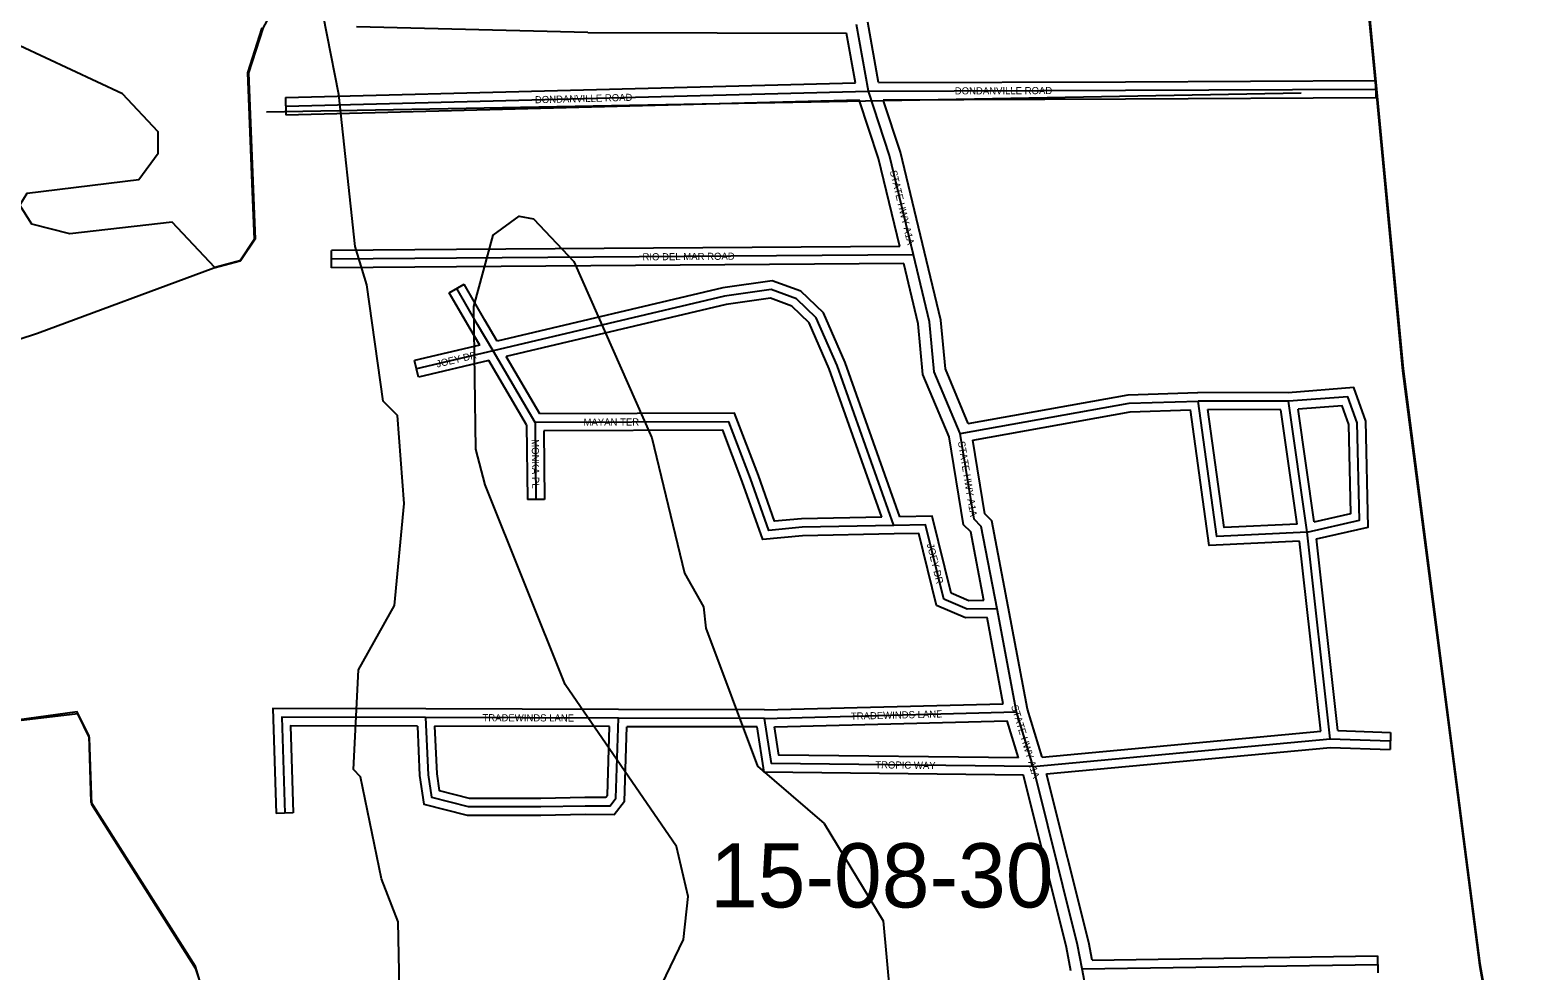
# Model space of a CAD drawing. Extents: x 418523 to 616617, y 1878279 to 2196743.
# Drawn here: x 568098 to 573384, y 1989941 to 1993241 of the extents above; entities that cross this region are included whole.
import ezdxf

# ---------------------------------------------------------------- set-up
doc = ezdxf.new("R2010")
doc.units = 0
for name, color, linetype in [('Level 1', 7, 'Continuous'), ('Level 2', 7, 'Continuous'), ('Level 22', 7, 'Continuous'), ('Level 23', 7, 'Continuous'), ('Level 31', 7, 'Continuous'), ('Level 32', 7, 'Continuous'), ('Level 34', 7, 'Continuous'), ('Level 5', 7, 'Continuous'), ('Level 7', 7, 'Continuous'), ('Level 8', 7, 'Continuous')]:
    doc.layers.add(name, color=color, linetype=linetype)

msp = doc.modelspace()

# ---------------------------------------------------------------- linework, layer by layer
at = {"layer": 'Level 1'}
msp.add_line((572554.585, 1993020.008), (568926.609, 1992952.584), dxfattribs=at)
at = {"layer": 'Level 22'}
for p, q in [((571037.193, 1993026.716), (570995.871, 1993260.28)), ((571556.415, 1990849.401), (571488.107, 1991210.667)), ((571614.332, 1990657.621), (571556.415, 1990849.401))]:
    msp.add_line(p, q, dxfattribs=at)
for points in [[(571195.387, 1992452.501), (571111.516, 1992801.441), (571037.193, 1993026.716)], [(571358.857, 1991825.544), (571267.7, 1992042.493), (571251.613, 1992217.449), (571195.387, 1992452.501)], [(571488.107, 1991210.667), (571432.954, 1991500.265), (571408.274, 1991525.051), (571358.857, 1991825.544)], [(571786.51, 1989948.824), (571770.843, 1990032.137), (571614.332, 1990657.621)], [(572009.84, 1988997.717), (571869.755, 1989598.069), (571844.796, 1989639.947), (571786.51, 1989948.824)]]:
    msp.add_lwpolyline(points, dxfattribs=at)
at = {"layer": 'Level 23'}
for p, q in [((571072.487, 1993056.834), (571035.009, 1993268.671)), ((570991.47, 1993055.547), (570960.539, 1993230.374)), ((571510.256, 1990878.225), (571453.148, 1991180.257)), ((571595.325, 1990858.924), (571527.412, 1991218.099)), ((571563.304, 1990688.226), (571523.946, 1990818.556)), ((571646.122, 1990690.718), (571595.324, 1990858.923))]:
    msp.add_line(p, q, dxfattribs=at)
for points in [[(571147.12, 1992482.155), (571073.01, 1992790.481), (571005.245, 1992995.881)], [(571234.279, 1992461.849), (571150.022, 1992812.4), (571089.156, 1992996.889)], [(571387.287, 1991861.144), (571306.969, 1992052.3), (571291.183, 1992223.966), (571234.289, 1992461.806)], [(571320.153, 1991814.397), (571228.433, 1992032.687), (571212.043, 1992210.931), (571161.493, 1992422.254)], [(571441.777, 1991240.13), (571395.954, 1991480.732), (571370.884, 1991505.91), (571320.153, 1991814.397)], [(571527.402, 1991218.151), (571469.954, 1991519.797), (571445.664, 1991544.191), (571403.099, 1991803.025)], [(571747.199, 1989941.432), (571731.75, 1990023.578), (571580.506, 1990628.017)], [(571821.476, 1989979.336), (571809.935, 1990040.696), (571661.994, 1990631.936)]]:
    msp.add_lwpolyline(points, dxfattribs=at)
at = {"layer": 'Level 31'}
for p, q in [((568994.381, 1992974.052), (571037.193, 1993026.716)), ((571195.387, 1992452.501), (569593.469, 1992440.97)), ((569593.469, 1992440.97), (569155.17, 1992437.641)), ((569721.149, 1992115.924), (569453.329, 1992052.916)), ((569868.668, 1991865.018), (569721.149, 1992115.924)), ((572509.728, 1991938.911), (572192.9, 1991939.997)), ((572575.288, 1991480.191), (572509.728, 1991938.911)), ((569868.668, 1991865.018), (569871.523, 1991594.815)), ((572656.419, 1990754.878), (572575.288, 1991480.191)), ((570160.875, 1990827.913), (569485.018, 1990829.866)), ((570672.764, 1990826.718), (570160.875, 1990827.913)), ((570672.764, 1990826.718), (571556.415, 1990849.401)), ((571614.332, 1990657.621), (572656.419, 1990754.878)), ((572656.419, 1990754.878), (572866.995, 1990747.854)), ((571786.51, 1989948.824), (572822.721, 1989963.914))]:
    msp.add_line(p, q, dxfattribs=at)
for points in [[(571037.193, 1993026.716), (571938.505, 1993029.729), (572815.719, 1993034.272)], [(569721.149, 1992115.924), (569666.818, 1992208.421), (569593.854, 1992334.781)], [(571126.594, 1991503.882), (570927.769, 1992064.01), (570854.58, 1992231.461), (570784.647, 1992298.9), (570696.873, 1992331.106), (570532.855, 1992307.851), (569721.149, 1992115.924)], [(571358.857, 1991825.544), (571951.216, 1991932.186), (572192.9, 1991939.997)], [(572575.288, 1991480.191), (572258.418, 1991464.55), (572192.9, 1991939.997)], [(572575.288, 1991480.191), (572758.694, 1991521.595), (572751.224, 1991863.447), (572718.131, 1991955.164), (572509.728, 1991938.911)], [(571126.594, 1991503.882), (570804.671, 1991497.356), (570687.616, 1991485.991), (570623.339, 1991667.969), (570547.371, 1991867.43), (569868.668, 1991865.018)], [(571488.107, 1991210.667), (571383.76, 1991209.454), (571302.017, 1991244.917), (571237.603, 1991506.171), (571126.594, 1991503.882)], [(569485.018, 1990829.866), (568980.424, 1990831.424), (568990.727, 1990494.655)], [(569485.018, 1990829.866), (569493.743, 1990629.471), (569505.609, 1990550.166), (569634.299, 1990517.498), (569888.661, 1990517.626), (570043.759, 1990520.536), (570131.612, 1990520.33), (570151.972, 1990546.829), (570160.875, 1990827.913)], [(571614.332, 1990657.621), (570697.135, 1990668.471), (570672.764, 1990826.718)]]:
    msp.add_lwpolyline(points, dxfattribs=at)
at = {"layer": 'Level 32'}
for p, q in [((570053.59, 1993232.839), (569242.097, 1993251.894)), ((570053.59, 1993232.84), (570960.54, 1993230.374)), ((568993.608, 1993004.043), (570991.47, 1993055.548)), ((572815.564, 1993064.273), (572815.874, 1993004.271)), ((568993.608, 1993004.043), (568995.154, 1992944.061)), ((568995.154, 1992944.061), (571005.245, 1992995.881)), ((569593.242, 1992470.968), (569154.943, 1992467.641)), ((569155.398, 1992407.641), (569154.943, 1992467.641)), ((571147.12, 1992482.155), (569593.254, 1992470.97)), ((569593.698, 1992410.97), (569155.398, 1992407.641)), ((571161.493, 1992422.254), (569593.686, 1992410.969)), ((569567.874, 1992319.78), (569619.834, 1992349.783)), ((569674.676, 1992135.81), (569446.46, 1992082.119)), ((569460.2, 1992023.711), (569446.46, 1992082.119)), ((569706.495, 1992081.656), (569460.2, 1992023.711)), ((569838.755, 1991856.706), (569706.496, 1992081.656)), ((569885.795, 1991895.079), (569767.616, 1992096.082)), ((572508.611, 1991968.915), (572192.467, 1991969.999)), ((572483.699, 1991908.999), (572227.336, 1991909.878)), ((572540.933, 1991508.532), (572483.699, 1991908.999)), ((572600.389, 1991516.613), (572543.954, 1991911.487)), ((569838.755, 1991856.706), (569841.524, 1991594.497)), ((569898.987, 1991835.124), (569901.522, 1991595.131)), ((569901.522, 1991595.131), (569841.524, 1991594.497)), ((572623.208, 1990781.908), (572548.609, 1991448.836)), ((572683.349, 1990783.996), (572608.088, 1991456.84)), ((570672.414, 1990856.719), (571510.256, 1990878.226)), ((570160.962, 1990857.913), (569485.104, 1990859.866)), ((570672.415, 1990856.719), (570160.945, 1990857.913)), ((570707.604, 1990797.601), (571523.946, 1990818.555)), ((570129.913, 1990798.001), (569516.358, 1990799.775)), ((570647.021, 1990796.777), (570189.939, 1990797.844)), ((571646.123, 1990690.718), (572623.208, 1990781.909)), ((572683.35, 1990783.996), (572867.995, 1990777.837)), ((572867.995, 1990777.837), (572865.996, 1990717.87)), ((571661.993, 1990631.936), (572657.316, 1990724.83)), ((572657.317, 1990724.831), (572865.996, 1990717.87)), ((569020.713, 1990495.572), (568960.74, 1990493.738)), ((571821.476, 1989979.337), (572822.285, 1989993.911)), ((572822.285, 1989993.911), (572823.159, 1989933.916))]:
    msp.add_line(p, q, dxfattribs=at)
for points in [[(571072.487, 1993056.834), (571938.378, 1993059.73), (572815.564, 1993064.273)], [(571089.155, 1992996.889), (571938.634, 1992999.728), (572815.874, 1993004.271)], [(569735.8, 1992150.215), (569692.743, 1992223.518), (569619.834, 1992349.783)], [(571147.624, 1991534.321), (570955.686, 1992075.049), (570879.687, 1992248.926), (570800.919, 1992324.886), (570700.127, 1992361.868), (570527.286, 1992337.361), (569735.8, 1992150.216)], [(569674.676, 1992135.81), (569640.894, 1992193.322), (569567.874, 1992319.78)], [(571084.413, 1991533.033), (570899.854, 1992052.971), (570829.473, 1992213.996), (570768.374, 1992272.914), (570693.619, 1992300.344), (570538.424, 1992278.339), (569767.617, 1992096.081)], [(572608.088, 1991456.84), (572789.224, 1991497.731), (572781.109, 1991869.011), (572738.592, 1991986.852), (572508.612, 1991968.915)], [(571387.287, 1991861.144), (571948.058, 1991962.101), (572192.468, 1991969.999)], [(572600.389, 1991516.613), (572728.165, 1991545.458), (572721.337, 1991857.884), (572697.67, 1991923.476), (572543.954, 1991911.487)], [(571084.413, 1991533.033), (570802.914, 1991527.327), (570708.085, 1991518.121), (570651.506, 1991678.306), (570568.019, 1991897.504), (569885.796, 1991895.079)], [(571403.099, 1991803.025), (571954.375, 1991902.272), (572166.869, 1991909.139)], [(572548.608, 1991448.836), (572232.449, 1991433.231), (572166.869, 1991909.139)], [(572540.932, 1991508.533), (572284.386, 1991495.869), (572227.336, 1991909.877)], [(571127.203, 1991473.887), (570806.428, 1991467.385), (570667.147, 1991453.862), (570595.174, 1991657.633), (570526.723, 1991837.356), (569898.987, 1991835.125)], [(571441.776, 1991240.13), (571389.82, 1991239.527), (571327.588, 1991266.526), (571260.984, 1991536.661), (571147.624, 1991534.322)], [(571453.148, 1991180.257), (571377.699, 1991179.381), (571276.445, 1991223.309), (571214.221, 1991475.681), (571127.214, 1991473.888)], [(569485.11, 1990859.867), (568949.489, 1990861.521), (568960.74, 1990493.738)], [(569456.291, 1990799.954), (569011.359, 1990801.328), (569020.713, 1990495.572)], [(569456.292, 1990799.954), (569463.839, 1990626.591), (569478.89, 1990525.996), (569630.557, 1990487.496), (569888.949, 1990487.626), (570044.005, 1990490.534), (570146.369, 1990490.294), (570181.651, 1990536.216), (570189.939, 1990797.844)], [(569516.357, 1990799.775), (569523.647, 1990632.351), (569532.327, 1990574.336), (569638.039, 1990547.501), (569888.372, 1990547.627), (570043.513, 1990550.537), (570116.855, 1990550.365), (570122.293, 1990557.441), (570129.914, 1990798.001)], [(571580.506, 1990628.017), (570671.354, 1990638.774), (570647.021, 1990796.777)], [(571563.304, 1990688.226), (570722.916, 1990698.17), (570707.603, 1990797.601)]]:
    msp.add_lwpolyline(points, dxfattribs=at)
at = {"layer": 'Level 5'}
for points in [[(572465.57, 1998189.806), (572518.829, 1996605.731), (572551.753, 1996480.558), (572654.735, 1994812.961), (572736.049, 1994170.798), (572726.405, 1993770.689), (572751.346, 1993745.579), (572912.59, 1992052.782), (573180.964, 1989967.808), (573303.759, 1989275.465), (573319.554, 1989000.338), (573638.437, 1987065.259)], [(569024.013, 1993449.195), (568914.994, 1993249.488), (568864.445, 1993091.254), (568887.567, 1992507.611), (568837.317, 1992432.749), (568745.525, 1992408.037), (568595.989, 1992566.919), (568237.391, 1992526.413), (568104.107, 1992560.182), (568062.654, 1992627.003), (568087.794, 1992668.585), (568479.773, 1992717.361), (568546.753, 1992808.834), (568546.982, 1992883.866), (568422.396, 1993017.637), (567881.319, 1993269.496), (567615.169, 1993453.746), (567507.125, 1993562.477), (567315.679, 1993654.797)], [(568927.792, 1989473.052), (568712.25, 1989848.878), (568679.237, 1989949.011), (568314.299, 1990525.399), (568306.714, 1990758.844), (568265.291, 1990842.336), (567848.313, 1990793.699), (567815.031, 1990810.469)]]:
    msp.add_lwpolyline(points, dxfattribs=at)
at = {"layer": 'Level 7'}
for points in [[(568927.792, 1989473.052), (569395.578, 1989763.286), (569388.381, 1990113.453), (569330.487, 1990263.696), (569256.629, 1990622.393), (569231.688, 1990647.493), (569249.502, 1990997.561), (569375.271, 1991222.248), (569409.785, 1991580.576), (569385.759, 1991889.123), (569335.898, 1991939.304), (569278.889, 1992347.952), (569237.625, 1992481.495), (569181.004, 1993015.186), (569098.975, 1993432.265), (569024.013, 1993449.195)], [(570312.997, 1989893.73), (570388.546, 1990051.855), (570405.674, 1990201.848), (570364.579, 1990377.071), (569974.6, 1990945.19), (569693.421, 1991646.352), (569660.498, 1991771.534), (569653.759, 1992271.716), (569721.266, 1992521.612), (569813.167, 1992588.005), (569863.179, 1992579.506), (570004.414, 1992428.994), (570277.522, 1991811.183), (570392.694, 1991335.654), (570458.997, 1991218.722), (570467.099, 1991143.691), (570648.931, 1990659.561), (570881.7, 1990458.74), (571089.002, 1990116.295), (571113.157, 1989849.429)]]:
    msp.add_lwpolyline(points, dxfattribs=at)
at = {"layer": 'Level 8'}
for points in [[(570620.753, 1994488.288), (570630.753, 1994458.288), (570746.764, 1994020.279), (570831.765, 1994052.281), (571006.769, 1994110.285), (572423.801, 1994148.304), (572648.807, 1994147.306), (572723.808, 1994164.308), (572722.815, 1993764.299), (572747.816, 1993739.298), (572815.83, 1993034.283), (572909.85, 1992046.262), (573078.878, 1990741.235), (573179.894, 1989961.218), (573302.909, 1989269.204), (573318.914, 1988994.198), (573638.957, 1987059.159)], [(567841.729, 1992085.198), (568124.734, 1992178.204), (568742.745, 1992407.217), (568834.747, 1992432.219), (568884.746, 1992507.221), (568877.744, 1992674.225), (568866.738, 1992971.231), (568861.735, 1993091.234), (568911.734, 1993249.238)], [(568710.789, 1989848.158), (568677.787, 1989957.161), (568312.768, 1990533.169), (568304.764, 1990766.174), (568263.761, 1990850.176), (567846.753, 1990793.169)]]:
    msp.add_lwpolyline(points, dxfattribs=at)

# ---------------------------------------------------------------- texts
at = {"layer": 'Level 2'}
msp.add_text('15-08-30', height=225, dxfattribs=at).set_placement((570481.759, 1990163.793))
at = {"layer": 'Level 34'}
for s, height, rotation, p in [('DONDANVILLE ROAD', 25, 0.190769, (571340.018, 1993015.231)), ('DONDANVILLE ROAD', 25, 1.476039, (569868.282, 1992984.08)), ('STATE HWY A1A', 25, 283.514122, (571112.023, 1992745.858)), ('RIO DEL MAR ROAD', 24.99916, 0.411706, (570245.236, 1992433.164)), ('JOEY DR', 25, 13.238131, (569525.257, 1992056.998)), ('MAYAN TER', 25, 0.202836, (570038.372, 1991853.416)), ('MONKA PL', 25, 270.604344, (569856.793, 1991805.843)), ('STATE HWY A1A', 25, 279.337908, (571350.904, 1991796.886)), ('JOEY DR', 24.9992, 283.849342, (571241.727, 1991437.227)), ('STATE HWY A1A', 25, 286.802975, (571537.192, 1990869.825)), ('TRADEWINDS LANE', 25, 359.833722, (569684.012, 1990816.794)), ('TRADEWINDS LANE', 25, 1.46965, (570976.059, 1990822.001)), ('TROPIC WAY', 24.9992, 359.321467, (571061.108, 1990651.666))]:
    msp.add_text(s, height=height, rotation=rotation, dxfattribs=at).set_placement(p)

doc.saveas('drawing.dxf')
